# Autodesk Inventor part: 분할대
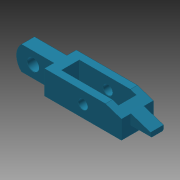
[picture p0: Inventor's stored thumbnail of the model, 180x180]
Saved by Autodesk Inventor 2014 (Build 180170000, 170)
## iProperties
Created: 2016-11
Part Number: 분할대
Material: 강철, 연강
Document SubType Name: Modeling
Designer: mduedu
Density: 1 g/cm^3
Appearance: 터키옥색
Author: mduedu
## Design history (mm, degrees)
sketch "스케치1"
  geometry: L1 (32.5, 13.5)-(-32.5, 13.5); L2 (-32.5, 13.5)-(-32.5, -13.5); L3 (-32.5, -13.5)-(32.5, -13.5); L4 (32.5, -13.5)-(32.5, 13.5); L5 (24, 7.5)-(-24, 7.5); L6 (-24, 7.5)-(-24, -7.5); L7 (-24, -7.5)-(24, -7.5); L8 (24, -7.5)-(24, 7.5); L9 (24, 0)-(-24, 0); L10 (0, -13.5)-(0, 13.5); 4 further points
  constraints: 20 end point, 7 midpoint, 4 parallel, 2 coincident, 2 horizontal, 2 perpendicular, 1 horizontal alignment
  dimensions: "d0" = 15 distance of L5.end L6.end; "d2" = 27 distance between parallel lines of L1 L3; "d3" = 48 distance of L5.start L5.end; "d4" = 65 distance of L1.start L1.end
extrude "돌출1" new body sketch "스케치1" distance "d5" = 20; taper "d6" = 0 deg
sketch "스케치2"
  geometry: L1 (0, 0)-(65, 0) reference; L2 (65, 0)-(65, 20) reference; L3 (0, 20)-(65, 20) reference; L4 (0, 0)-(0, 20) reference; L5 (32.5, 0)-(32.5, 20); C1 r 4 at (32.5, 10)
  constraints: 2 end point, 2 midpoint, 1 centre point
  dimensions: "d7" = 8 diameter of C1
extrude "돌출2" cut sketch "스케치2" stored distance "d8" = 20; taper "d9" = 0 deg
chamfer "모따기1" distance "d10" = 0.2; stored, may be unused: second distance "d11" = 2, angle "d12" = 45 deg
sketch "스케치3"
  geometry: L1 (-32.5, 0)-(-32.5, 20) reference; L2 (-32.5, 20)-(-59.798, 20); L3 (-64, 20)-(-64, 0); L4 (-64, 0)-(-59.798, 0); L5 (-32.5, 0)-(-32.5, 20); L6 (-59.798, 20)-(-64, 20); L7 (-59.798, 0)-(-32.5, 0); C1 r 4.2 at (0, 10) reference; C2 r 5 at (-50, 10); A1 r 14 centre (-50, 10) between (-59.798, 20) and (-59.798, 0); 1 further point
  constraints: 12 end point, 5 parallel, 2 centre point, 2 horizontal, 2 perpendicular, 2 point on circle, 1 coincident, 1 horizontal alignment, 1 tangent
  dimensions: "d13" = 64 distance from line of L3 C1.centre; "d14" = 14 radius of A1; "d15" = 10 diameter of C2
extrude "돌출3" join sketch "스케치3" stored distance "d16" = 11; taper "d17" = 0 deg
sketch "스케치4"
  geometry: L1 (32.5, 0)-(32.5, 20) reference; L2 (32.5, 20)-(49, 20); L3 (49, 20)-(49, 6); L4 (49, 6)-(32.5, 6); L5 (32.5, 6)-(32.5, 20); L6 (32.5, 0)-(-32.5, 0) reference; 1 further point
  constraints: 8 end point, 2 parallel, 1 horizontal, 1 perpendicular
  dimensions: "d18" = 16.5 distance of L1.end L2.end; "d19" = 6 distance between parallel lines of L4 L6
extrude "돌출4" join sketch "스케치4" stored distance "d20" = 11; taper "d21" = 0 deg
chamfer "모따기2" distance "d22" = 30; stored, may be unused: second distance "d23" = 10, angle "d24" = 45 deg
chamfer "모따기3" distance "d25" = 1; stored, may be unused: second distance "d26" = 10, angle "d27" = 45 deg
chamfer "모따기4" distance "d28" = 0.2; stored, may be unused: second distance "d29" = 10, angle "d30" = 45 deg
node "솔리드1"
node "투영된 루프1"
